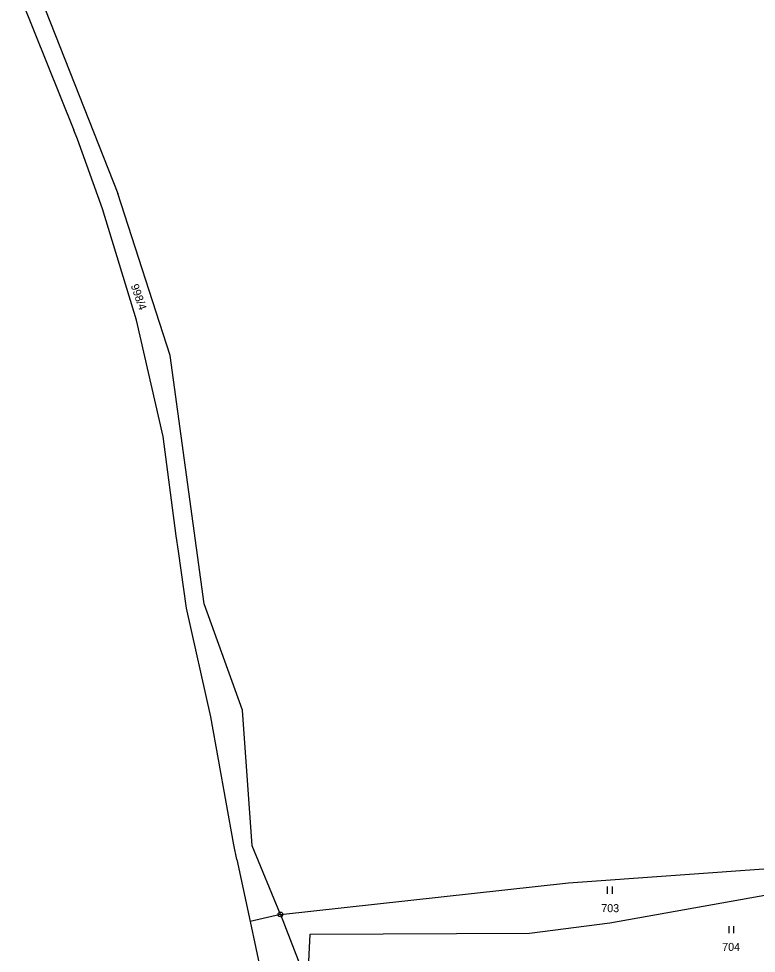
# Model space of a CAD drawing. Extents: x -754970 to -752637, y -970569 to -968179.
# Drawn here: x -754677.4 to -754520.7, y -969678.2 to -969479.8 of the extents above; entities that cross this region are included whole.
import ezdxf
from ezdxf.enums import TextEntityAlignment as Align

# ---------------------------------------------------------------- set-up
doc = ezdxf.new("R2010")
doc.units = 0
doc.header["$LTSCALE"] = 0.68
for name, color, linetype, lineweight in [('1', 7, 'Continuous', 25), ('3', 7, 'Continuous', 25), ('8', 7, 'Continuous', 25)]:
    doc.layers.add(name, color=color, linetype=linetype, lineweight=lineweight)
doc.layers.add('2', color=7, linetype='Continuous')

msp = doc.modelspace()

# ---------------------------------------------------------------- linework, layer by layer
at = {"layer": '1'}
for p, q in [((-754677.41, -969474.21), (-754665.71, -969503.46)), ((-754673.25, -969474.05), (-754656.35, -969516.92)), ((-754664.94, -969505.37), (-754665.71, -969503.46)), ((-754659.57, -969520.13), (-754664.94, -969505.37)), ((-754645.22, -969551.29), (-754656.35, -969516.92)), ((-754652.37, -969543.76), (-754659.57, -969520.13)), ((-754646.73, -969568.49), (-754652.37, -969543.76)), ((-754638.01, -969604.04), (-754645.22, -969551.29)), ((-754643.96, -969589.57), (-754646.73, -969568.49)), ((-754629.87, -969626.58), (-754638.01, -969604.04)), ((-754636.57, -969628), (-754641.75, -969604.95)), ((-754631.73, -969655.16), (-754636.57, -969628)), ((-754627.79, -969655.37), (-754629.87, -969626.58)), ((-754631.07, -969658.27), (-754631.73, -969655.16)), ((-754621.81, -969669.94), (-754627.79, -969655.37)), ((-754551.86, -969671.72), (-754461.92, -969655.77)), ((-754631.07, -969658.27), (-754628.26, -969671.46)), ((-754560.6, -969663.25), (-754495.4, -969658.57)), ((-754621.81, -969669.94), (-754560.6, -969663.25)), ((-754621.81, -969669.94), (-754628.26, -969671.46)), ((-754621.81, -969669.94), (-754616.05, -969684.73)), ((-754628.26, -969671.46), (-754622.1, -969700.37)), ((-754568.88, -969673.93), (-754551.86, -969671.72)), ((-754616.05, -969684.73), (-754615.48, -969674.12)), ((-754615.48, -969674.12), (-754568.88, -969673.93))]:
    msp.add_line(p, q, dxfattribs=at)
msp.add_lwpolyline([(-754641.75, -969604.95), (-754643.49, -969592.86), (-754643.96, -969589.57)], dxfattribs=at)
at = {"layer": '3'}
for p, q in [((-754552.301, -969665.56), (-754552.301, -969664.06)), ((-754551.3, -969665.56), (-754551.3, -969664.06)), ((-754526.481, -969673.92), (-754526.481, -969672.42)), ((-754525.48, -969673.92), (-754525.48, -969672.42))]:
    msp.add_line(p, q, dxfattribs=at)
at = {"layer": '8'}
for radius in [0.5, 0.0303]:
    msp.add_circle((-754621.81, -969669.9399), radius, dxfattribs=at)

# ---------------------------------------------------------------- texts
at = {"layer": '2'}
msp.add_text('998/4', height=1.7, rotation=289, dxfattribs=at).set_placement((-754652.7032, -969539.1283), align=Align.CENTER)
for s, p in [('703', (-754551.759, -969669.475)), ('704', (-754526.069, -969677.695))]:
    msp.add_text(s, height=1.7, dxfattribs=at).set_placement(p, align=Align.CENTER)

doc.saveas('drawing.dxf')
